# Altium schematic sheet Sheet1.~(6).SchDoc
size A4
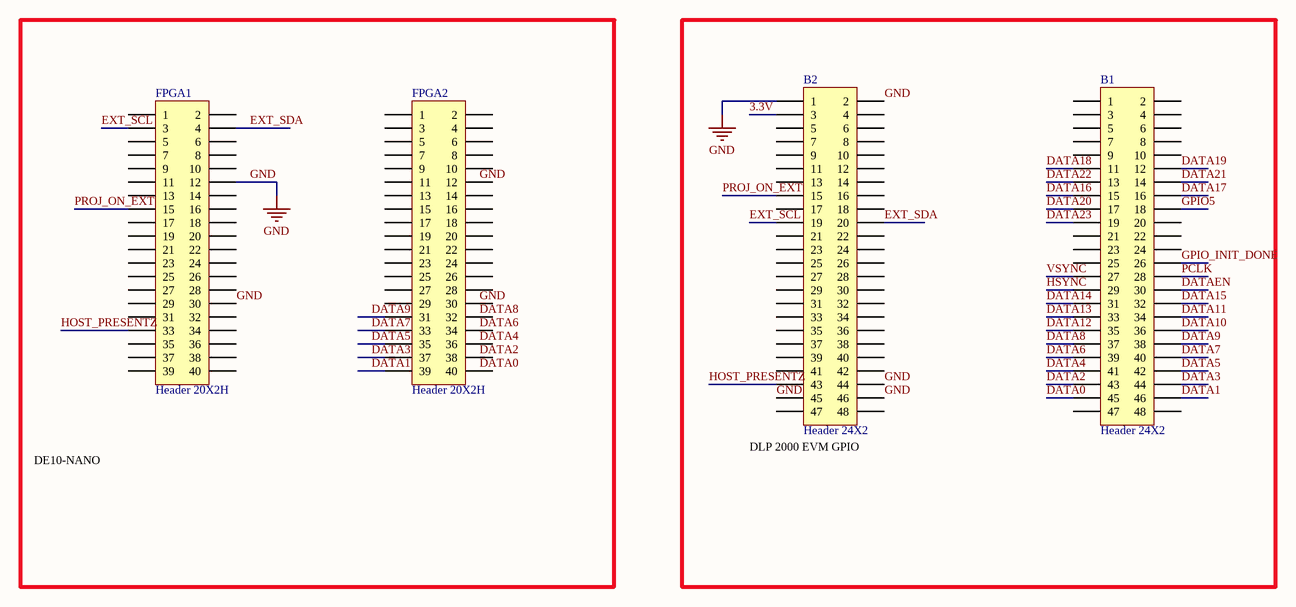
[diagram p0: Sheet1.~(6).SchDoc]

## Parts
B1  Header 24X2  [HDR2X24]
B2  Header 24X2  [HDR2X24]
FPGA1  Header 20X2H  [HDR2X20H]
FPGA2  Header 20X2H  [HDR2X20H]

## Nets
GND: B2.1 B2.2 B2.44 B2.45 B2.46 FPGA1.12 FPGA1.30
3.3V: B2.3
DATA0: B1.45
DATA1: B1.46 FPGA2.39
DATA2: B1.43
DATA3: B1.44 FPGA2.37
DATA4: B1.41
DATA5: B1.42 FPGA2.35
DATA6: B1.39
DATA7: B1.40 FPGA2.33
DATA8: B1.37
DATA9: B1.38 FPGA2.31
DATA10: B1.36
DATA11: B1.34
DATA12: B1.35
DATA13: B1.33
DATA14: B1.31
DATA15: B1.32
DATA16: B1.15
DATA17: B1.16
DATA18: B1.11
DATA19: B1.12
DATA20: B1.17
DATA21: B1.14
DATA22: B1.13
DATA23: B1.19
DATAEN: B1.30
EXT_SCL: B2.19 FPGA1.3
EXT_SDA: B2.20 FPGA1.4
GPIO5: B1.18
GPIO_INIT_DONE: B1.26
HOST_PRESENTZ: B2.43 FPGA1.33
HSYNC: B1.29
PCLK: B1.28
PROJ_ON_EXT: B2.15 FPGA1.15
VSYNC: B1.27

Not connected (* = marked no-connect by the designer): B1 1 2 3 4 5 6 7 8 9 10 20 21 22 23 24 25 47 48; B2 4 5 6 7 8 9 10 11 12 13 14 16 17 18 21 22 23 24 25 26 27 28 29 30 31 32 33 34 35 36 37 38 39 40 41 42 47 48; FPGA1 1 2 5 6 7 8 9 10 11 13 14 16 17 18 19 20 21 22 23 24 25 26 27 28 29 31 32 34 35 36 37 38 39 40; FPGA2 1 2 3 4 5 6 7 8 9 10 11 12 13 14 15 16 17 18 19 20 21 22 23 24 25 26 27 28 29 30 32 34 36 38 40

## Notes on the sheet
- DE10-NANO
- DLP 2000 EVM GPIO
- Labels drawn without touching a wire or pin: DATA0, DATA2, DATA4, DATA6, DATA8, GND

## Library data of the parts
B1 B2 = Header 24X2: Header, 24-Pin, Dual row
FPGA1 FPGA2 = Header 20X2H: Header, 20-Pin, Dual row, Right Angle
